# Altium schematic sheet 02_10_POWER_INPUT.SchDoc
size 289 x 396 mm
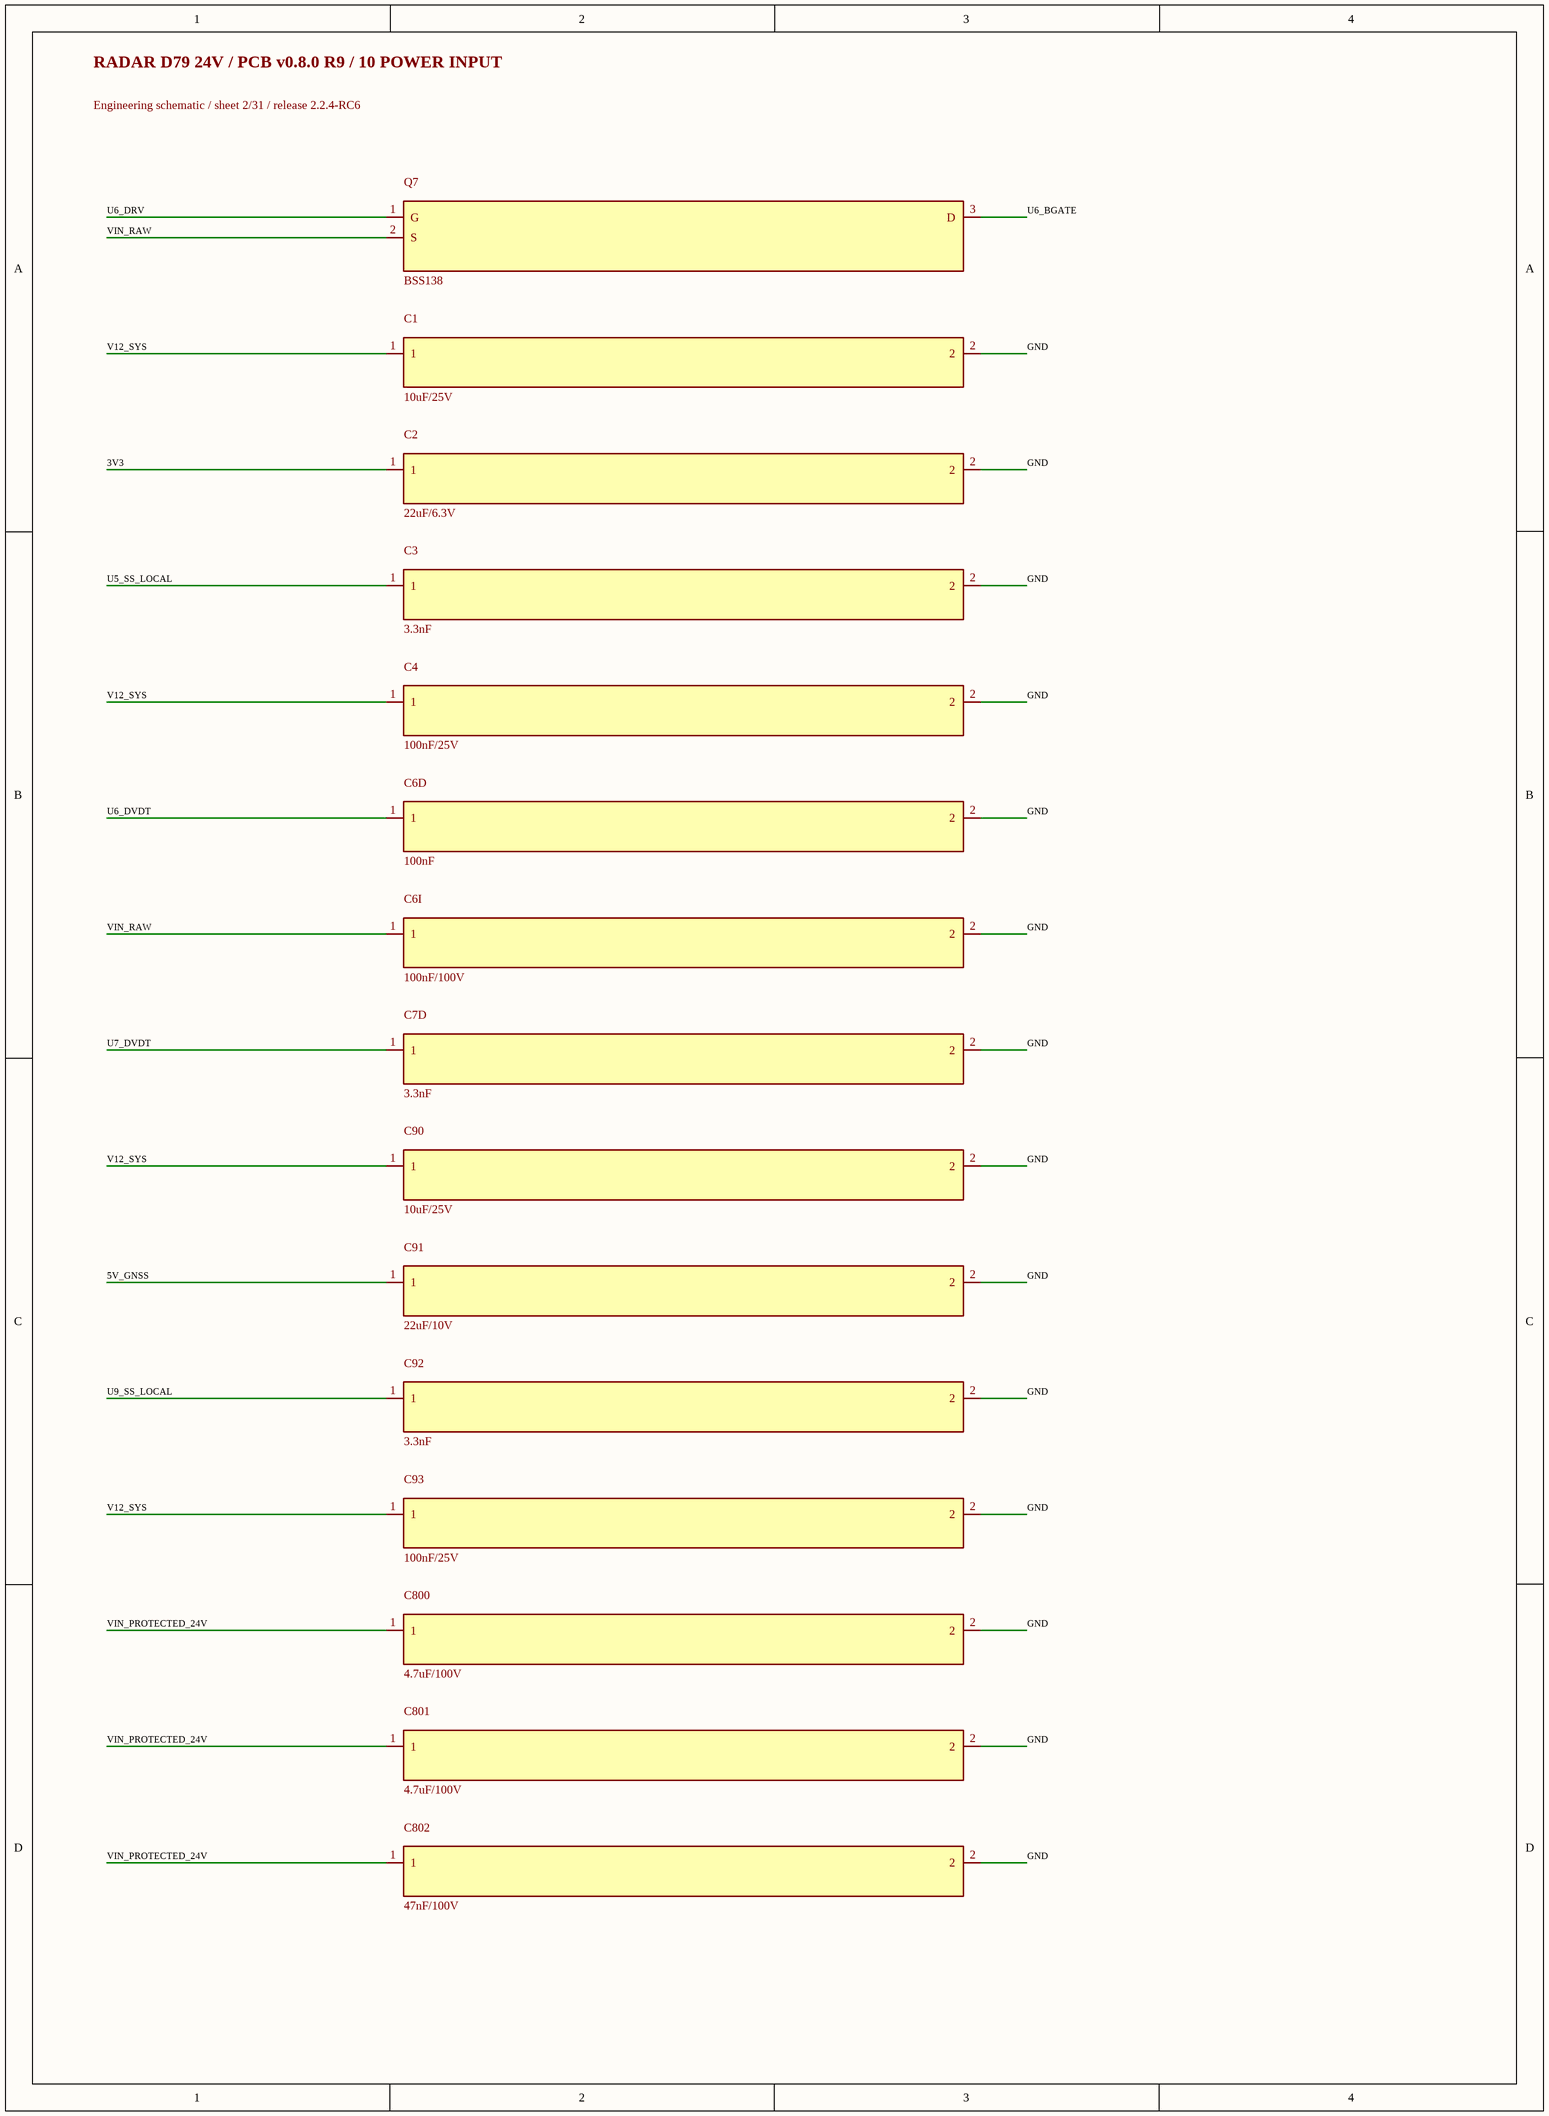
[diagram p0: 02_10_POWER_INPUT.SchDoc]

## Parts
C1  10uF/25V  [C_1206_3216Metric]
C2  22uF/6.3V  [C_1206_3216Metric]
C3  3.3nF  [C_0603_1608Metric]
C4  100nF/25V  [C_0603_1608Metric]
C6D  100nF  [C_0603_1608Metric]
C6I  100nF/100V  [C_0603_1608Metric]
C7D  3.3nF  [C_0603_1608Metric]
C90  10uF/25V  [C_1206_3216Metric]
C91  22uF/10V  [C_1206_3216Metric]
C92  3.3nF  [C_0603_1608Metric]
C93  100nF/25V  [C_0603_1608Metric]
C800  4.7uF/100V  [C_1210_3225Metric]
C801  4.7uF/100V  [C_1210_3225Metric]
C802  47nF/100V  [C_0603_1608Metric]
Q7  BSS138  [SOT-23]

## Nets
3V3: C2.1
5V_GNSS: C91.1
GND: C1.2 C2.2 C3.2 C4.2 C6D.2 C6I.2 C7D.2 C90.2 C91.2 C92.2 C93.2 C800.2 C801.2 C802.2
U5_SS_LOCAL: C3.1
U6_BGATE: Q7.3(D)
U6_DRV: Q7.1(G)
U6_DVDT: C6D.1
U7_DVDT: C7D.1
U9_SS_LOCAL: C92.1
V12_SYS: C1.1 C4.1 C90.1 C93.1
VIN_PROTECTED_24V: C800.1 C801.1 C802.1
VIN_RAW: C6I.1 Q7.2(S)

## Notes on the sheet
- RADAR D79 24V / PCB v0.8.0 R9 / 10 POWER INPUT
- Engineering schematic / sheet 2/31 / release 2.2.4-RC6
